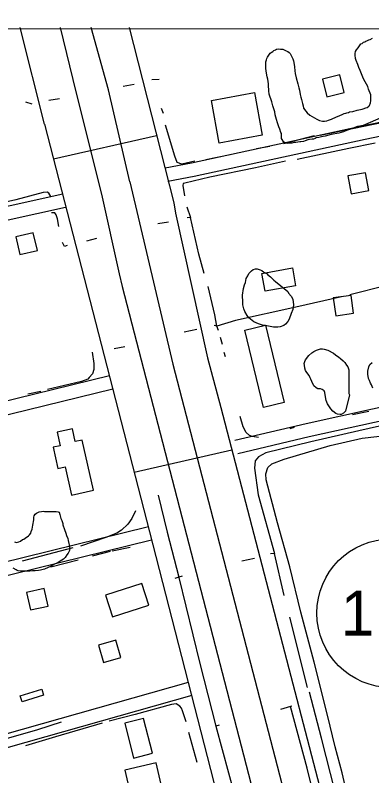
# Model space of a CAD drawing. Extents: x 3297753 to 3335611, y 652252 to 677623.
# Drawn here: x 3303757 to 3304548, y 674159 to 675847 of the extents above; entities that cross this region are included whole.
import ezdxf

# ---------------------------------------------------------------- set-up
doc = ezdxf.new("R2010")
doc.units = 0
for name, color, linetype in [('V-BLDG-OTLN', 7, 'Continuous'), ('V-DTCH-CNTR', 7, 'Continuous'), ('V-GRID-FRAM', 7, 'Continuous'), ('V-ROAD-CNTR', 7, 'Continuous'), ('V-ROAD-IDEN', 7, 'Continuous'), ('V-SITE-VEGE', 7, 'Continuous'), ('V-TOPO-SHOR', 7, 'Continuous')]:
    doc.layers.add(name, color=color, linetype=linetype)

msp = doc.modelspace()

# ---------------------------------------------------------------- linework, layer by layer
at = {"layer": 'V-BLDG-OTLN'}
for points in [[(3304448.3, 675666.1), (3304487.1, 675675.7), (3304477.5, 675714.5), (3304438.7, 675704.9)], [(3304287.5, 675675.3), (3304304.7, 675580.7), (3304209.3, 675563.3), (3304192.1, 675658)], [(3304534.4, 675497.5), (3304495.1, 675490.2), (3304502.4, 675450.9), (3304541.7, 675458.2)], [(3303767, 675315.9), (3303805.9, 675325.1), (3303796.6, 675364.1), (3303757.7, 675354.8)], [(3304379.1, 675246.7), (3304311.4, 675234.4), (3304304.3, 675273.7), (3304372, 675286)], [(3304462.7, 675219.7), (3304468.1, 675180.1), (3304507.8, 675185.5), (3304502.3, 675225.2)], [(3304307.6, 674976.1), (3304266.2, 675147.8), (3304312.4, 675158.9), (3304353.8, 674987.3)], [(3303930.2, 674792.8), (3303905.1, 674904.1), (3303890, 674900.7), (3303883.6, 674929.2), (3303849.5, 674921.5), (3303856.3, 674891.6), (3303840.6, 674888), (3303851.2, 674840.9), (3303867.6, 674844.6), (3303881.7, 674781.9)], [(3303820.5, 674574.7), (3303781.5, 674565.9), (3303790.4, 674526.9), (3303829.4, 674535.7)], [(3304037.9, 674585.7), (3303957, 674559.7), (3303972.3, 674511.8), (3304053.3, 674537.8)], [(3303952.9, 674410.3), (3303991.2, 674421.6), (3303979.9, 674460), (3303941.6, 674448.7)], [(3303819.7, 674337.8), (3303771.9, 674323.2), (3303767.8, 674336.6), (3303815.6, 674351.2)], [(3304061, 674208.8), (3304041.5, 674286.2), (3303999.8, 674275.7), (3304019.2, 674198.3)], [(3304087.4, 674110.8), (3304069.4, 674187.6), (3303999.7, 674171.3), (3304017.6, 674094.5)]]:
    msp.add_lwpolyline(points, close=True, dxfattribs=at)
at = {"layer": 'V-DTCH-CNTR'}
msp.add_lwpolyline([(3304563.6, 673850.9), (3304544.1, 673933.5), (3304517.4, 674019.1), (3304501.1, 674085.5), (3304482.7, 674165.2), (3304466.7, 674222.8), (3304449.5, 674293.3), (3304420, 674411.1), (3304390.5, 674521.8), (3304366.3, 674622.7), (3304338.5, 674720.1), (3304314, 674815.5), (3304313, 674829.1), (3304317, 674842.9), (3304325.9, 674851.3), (3304353.4, 674861.8), (3304455.8, 674891.9), (3304526.6, 674908.6), (3304585.3, 674914.6)], dxfattribs=at)
at = {"layer": 'V-GRID-FRAM'}
msp.add_lwpolyline([(3301859.6, 675814.9), (3333399.1, 675847), (3333425.5, 657662.7), (3301870.2, 657630.6), (3301859.6, 675814.9)], dxfattribs=at)
at = {"layer": 'V-ROAD-CNTR'}
for points in [[(3303821.3, 675605.4), (3303767.9, 675819.8)], [(3303856, 675819.9), (3303891, 675676.9), (3303948.2, 675450)], [(3304010.7, 675477.2), (3303963.9, 675681.3), (3303925, 675819.9)], [(3304009.8, 675820), (3304108.4, 675430.4)], [(3304089.7, 675508.3), (3304148.2, 675519), (3304527.1, 675601.4), (3304971.6, 675693.4), (3305454.6, 675794.1), (3305573.8, 675819.4)], [(3304095.1, 675478.8), (3304154.1, 675489.5), (3304533.3, 675572.1), (3304977.7, 675664.1), (3305460.7, 675764.7), (3305706.2, 675816.9)], [(3303821.3, 675605.4), (3304055, 674700.5), (3304303.9, 673729.3), (3304378.9, 673425.1)], [(3303841.2, 675528.3), (3304070.5, 675580.3)], [(3304244, 674903.5), (3304402.3, 674940.9), (3304844.1, 675038.3), (3305362.9, 675156.1), (3305778.6, 675248.1), (3306368, 675380.8), (3306791.3, 675474.1), (3306957.4, 675510.8), (3306994.4, 675513.7)], [(3304010.7, 675477.2), (3304106.3, 675072.8)], [(3303862, 675449.8), (3302685.8, 675189.6)], [(3303948.2, 675450), (3303987.5, 675272.7), (3303994.3, 675245)], [(3303868.5, 675420.5), (3302823, 675189.2)], [(3304108.4, 675430.4), (3304112.3, 675407.4), (3304183.2, 675086.4), (3304212.9, 674976)], [(3303994.3, 675245), (3304427.9, 673571.6)], [(3304250.9, 674874.3), (3304409, 674911.7), (3304850.7, 675009), (3305220.4, 675093)], [(3304106.3, 675072.8), (3304480.7, 673631.5)], [(3303965.9, 675046.3), (3303633.6, 674964.9)], [(3303973, 675017.2), (3303293.6, 674850.6)], [(3304212.9, 674976), (3304560.4, 673644.5)], [(3304020.9, 674832.5), (3304237.3, 674882.4)], [(3303010.3, 674455.3), (3304052.2, 674712)], [(3301875.7, 674135.6), (3301923.9, 674149.7), (3302004.8, 674177.6), (3302130.2, 674202.7), (3302342, 674257.5), (3302824.3, 674378.5), (3304059.4, 674682.9)], [(3304140.4, 674365.9), (3302754.4, 673973.9)], [(3304148.5, 674337), (3302762.8, 673945.1)]]:
    msp.add_lwpolyline(points, dxfattribs=at)
at = {"layer": 'V-ROAD-IDEN'}
msp.add_circle((3304591.1, 674519.8), 165, dxfattribs=at)
at = {"layer": 'V-SITE-VEGE'}
for p, q in [((3304526.8, 675784.3), (3304529.6, 675787.1)), ((3304529.6, 675787.1), (3304532.9, 675788.1)), ((3304532.9, 675788.1), (3304535.2, 675789.7)), ((3304535.2, 675789.7), (3304538.5, 675790.8)), ((3304538.5, 675790.8), (3304541.3, 675792.4)), ((3304541.3, 675792.4), (3304544.7, 675793.4)), ((3304544.7, 675793.4), (3304549.7, 675796.1)), ((3304330.7, 675768.4), (3304334, 675770)), ((3304334, 675770), (3304336.3, 675771.6)), ((3304336.3, 675771.6), (3304341.8, 675772.1)), ((3304341.8, 675772.1), (3304345.7, 675772)), ((3304345.7, 675772), (3304350.7, 675771.3)), ((3304350.7, 675771.3), (3304353.4, 675770.2)), ((3304353.4, 675770.2), (3304358.4, 675767.9)), ((3304512, 675766.8), (3304514.3, 675770.1)), ((3304514.3, 675770.1), (3304517.7, 675774.5)), ((3304517.7, 675774.5), (3304524, 675783.3)), ((3304524, 675783.3), (3304526.8, 675784.3)), ((3304314.8, 675750.9), (3304316.5, 675753.6)), ((3304316.5, 675753.6), (3304318.2, 675755.8)), ((3304318.2, 675755.8), (3304322.2, 675762.4)), ((3304322.2, 675762.4), (3304324.5, 675764.6)), ((3304324.5, 675764.6), (3304328.4, 675766.7)), ((3304328.4, 675766.7), (3304330.7, 675768.4)), ((3304358.4, 675767.9), (3304361.7, 675766.2)), ((3304361.7, 675766.2), (3304364.4, 675763.9)), ((3304364.4, 675763.9), (3304367.2, 675762.2)), ((3304367.2, 675762.2), (3304368.2, 675759.4)), ((3304368.2, 675759.4), (3304370.9, 675754.9)), ((3304370.9, 675754.9), (3304373.1, 675750.4)), ((3304511.3, 675758), (3304511.4, 675761.9)), ((3304511.8, 675751.3), (3304511.3, 675758)), ((3304511.4, 675761.9), (3304512, 675766.8)), ((3304312.8, 675733.2), (3304313, 675743.7)), ((3304313, 675743.7), (3304314.2, 675748.1)), ((3304314.2, 675748.1), (3304314.8, 675750.9)), ((3304373.1, 675750.4), (3304374.6, 675745.4)), ((3304374.6, 675745.4), (3304375.6, 675737.6)), ((3304375.6, 675737.6), (3304376.6, 675732.1)), ((3304513.3, 675746.3), (3304511.8, 675751.3)), ((3304517.1, 675737.9), (3304513.3, 675746.3)), ((3304519.2, 675731.2), (3304517.1, 675737.9)), ((3304312.8, 675728.7), (3304312.8, 675733.2)), ((3304313.8, 675723.2), (3304312.8, 675728.7)), ((3304314.3, 675718.7), (3304313.8, 675723.2)), ((3304376.6, 675732.1), (3304377, 675723.7)), ((3304377, 675723.7), (3304378, 675717.6)), ((3304522.4, 675724.5), (3304519.2, 675731.2)), ((3304525.6, 675717.2), (3304522.4, 675724.5)), ((3304315.8, 675710.4), (3304314.3, 675718.7)), ((3304317.4, 675705.4), (3304315.8, 675710.4)), ((3304318.8, 675694.8), (3304317.4, 675705.4)), ((3304378, 675717.6), (3304380.1, 675708.1)), ((3304380.1, 675708.1), (3304383.7, 675694.8)), ((3304529.8, 675705.5), (3304525.6, 675717.2)), ((3304533.6, 675698.8), (3304529.8, 675705.5)), ((3304318.7, 675687.6), (3304318.8, 675694.8)), ((3304319.7, 675683.7), (3304318.7, 675687.6)), ((3304383.7, 675694.8), (3304385.8, 675685.8)), ((3304385.8, 675685.8), (3304387.4, 675680.3)), ((3304539, 675688.7), (3304533.6, 675698.8)), ((3304541.1, 675682.6), (3304539, 675688.7)), ((3304319.7, 675679.2), (3304319.7, 675683.7)), ((3304320.6, 675672), (3304319.7, 675679.2)), ((3304326.4, 675654.7), (3304320.6, 675672)), ((3304387.4, 675680.3), (3304389.4, 675670.8)), ((3304389.4, 675670.8), (3304390.4, 675665.2)), ((3304545.8, 675670.3), (3304541.1, 675682.6)), ((3304546.3, 675663.6), (3304545.8, 675670.3)), ((3304328.5, 675645.8), (3304326.4, 675654.7)), ((3304390.4, 675665.2), (3304392, 675659.7)), ((3304392, 675659.7), (3304394.1, 675651.3)), ((3304394.1, 675651.3), (3304395.6, 675645.7)), ((3304543.2, 675646.5), (3304545.5, 675652.5)), ((3304545.5, 675652.5), (3304546.2, 675657)), ((3304546.2, 675657), (3304546.3, 675663.6)), ((3304332.7, 675632.4), (3304328.5, 675645.8)), ((3304395.6, 675645.7), (3304396.7, 675640.7)), ((3304396.7, 675640.7), (3304401.5, 675634)), ((3304505.8, 675633.3), (3304515.8, 675636.4)), ((3304515.8, 675636.4), (3304526.4, 675638.4)), ((3304526.4, 675638.4), (3304529.2, 675639.5)), ((3304529.2, 675639.5), (3304534.8, 675641.1)), ((3304534.8, 675641.1), (3304537.6, 675642.1)), ((3304537.6, 675642.1), (3304541.5, 675644.8)), ((3304541.5, 675644.8), (3304543.2, 675646.5)), ((3304333.7, 675625.7), (3304332.7, 675632.4)), ((3304336.3, 675615.2), (3304333.7, 675625.7)), ((3304401.5, 675634), (3304404.8, 675630.6)), ((3304404.8, 675630.6), (3304410.8, 675624.9)), ((3304410.8, 675624.9), (3304426.2, 675616.3)), ((3304458.4, 675616.3), (3304469.5, 675621.7)), ((3304469.5, 675621.7), (3304475.7, 675623.8)), ((3304475.7, 675623.8), (3304483.5, 675627.5)), ((3304483.5, 675627.5), (3304486.9, 675628.6)), ((3304486.9, 675628.6), (3304490.8, 675629.6)), ((3304490.8, 675629.6), (3304493, 675630.7)), ((3304493, 675630.7), (3304496.3, 675631.2)), ((3304496.3, 675631.2), (3304498.6, 675632.3)), ((3304498.6, 675632.3), (3304505.8, 675633.3)), ((3304571.6, 675620.4), (3304528.6, 675602.3)), ((3304338.9, 675608.5), (3304336.3, 675615.2)), ((3304342.1, 675599.5), (3304338.9, 675608.5)), ((3304426.2, 675616.3), (3304431.7, 675613.5)), ((3304431.7, 675613.5), (3304438.9, 675611.7)), ((3304438.9, 675611.7), (3304443.3, 675611.6)), ((3304443.3, 675611.6), (3304448.3, 675612.6)), ((3304448.3, 675612.6), (3304452.2, 675614.2)), ((3304452.2, 675614.2), (3304458.4, 675616.3)), ((3304521.9, 675600.8), (3304516.3, 675599.8)), ((3304528.6, 675602.3), (3304521.9, 675600.8)), ((3304344.2, 675593.9), (3304342.1, 675599.5)), ((3304346.3, 675586.7), (3304344.2, 675593.9)), ((3304347.4, 675584.5), (3304346.3, 675586.7)), ((3304347.8, 675577.2), (3304347.4, 675584.5)), ((3304475, 675585.5), (3304457.8, 675582.5)), ((3304485.6, 675588.1), (3304475, 675585.5)), ((3304491.7, 675590.8), (3304485.6, 675588.1)), ((3304506.8, 675596.6), (3304491.7, 675590.8)), ((3304516.3, 675599.8), (3304506.8, 675596.6)), ((3304347.8, 675573.4), (3304347.8, 675577.2)), ((3304352.6, 675564.9), (3304347.8, 675573.4)), ((3304396.5, 675566.9), (3304390.9, 675565.9)), ((3304400.4, 675568.5), (3304396.5, 675566.9)), ((3304406.5, 675570.1), (3304400.4, 675568.5)), ((3304409.9, 675571.1), (3304406.5, 675570.1)), ((3304415.4, 675571.6), (3304409.9, 675571.1)), ((3304418.7, 675572.1), (3304415.4, 675571.6)), ((3304422.7, 675573.7), (3304418.7, 675572.1)), ((3304424.9, 675574.8), (3304422.7, 675573.7)), ((3304430.5, 675575.8), (3304424.9, 675574.8)), ((3304436.6, 675577.3), (3304430.5, 675575.8)), ((3304444.4, 675578.9), (3304436.6, 675577.3)), ((3304457.8, 675582.5), (3304444.4, 675578.9)), ((3304356.4, 675562.7), (3304352.6, 675564.9)), ((3304362, 675562.6), (3304356.4, 675562.7)), ((3304366.4, 675563), (3304362, 675562.6)), ((3304370.3, 675563), (3304366.4, 675563)), ((3304375.3, 675564.5), (3304370.3, 675563)), ((3304379.8, 675564.5), (3304375.3, 675564.5)), ((3304388.7, 675566), (3304379.8, 675564.5)), ((3304390.9, 675565.9), (3304388.7, 675566))]:
    msp.add_line(p, q, dxfattribs=at)
for points in [[(3304361.5, 675233.6), (3304363.4, 675229.9), (3304368.9, 675223.4), (3304372.6, 675217.1), (3304374.2, 675204.2), (3304372.6, 675194.2), (3304369.3, 675184.7), (3304364.4, 675172.7), (3304362, 675167.4), (3304356.7, 675161.1), (3304352.5, 675158.3), (3304344.9, 675155.6), (3304339.3, 675154.9), (3304329.8, 675154.9), (3304311.5, 675158), (3304305.3, 675159.4), (3304296.7, 675162), (3304286.5, 675166.2), (3304275.2, 675175.2), (3304271.5, 675180.3), (3304266.4, 675189.2), (3304264.1, 675195), (3304262, 675204), (3304261.6, 675210.3), (3304260.9, 675225.6), (3304263.5, 675240.4), (3304265.6, 675248.5), (3304267.5, 675254), (3304268.4, 675258.4), (3304269.6, 675262.6), (3304272.9, 675268.9), (3304275.4, 675273.5), (3304281, 675279.7), (3304285, 675282.3), (3304289.8, 675283.9), (3304293.8, 675283.9), (3304300, 675282.2), (3304303.7, 675280.4), (3304308.8, 675276.9), (3304311.6, 675275.2), (3304315.5, 675272.7), (3304317.6, 675270.8), (3304323.6, 675266.2), (3304327.5, 675261.8), (3304330.5, 675259), (3304334.5, 675256)], [(3304489.7, 674968), (3304485.5, 674963.6), (3304480.1, 674960.8), (3304477.6, 674960.6), (3304472.3, 674961.3), (3304468.3, 674963.1), (3304461.9, 674968), (3304457.2, 674973.4), (3304449.8, 674984.3), (3304446.9, 674992.2), (3304445.3, 675000), (3304443.9, 675009.6), (3304442.3, 675013.5), (3304437.6, 675016.3), (3304434.2, 675017.5), (3304428.2, 675017.9), (3304424.7, 675020), (3304419.8, 675024.7), (3304414.8, 675033.7), (3304412.9, 675039.1), (3304411.5, 675042.3), (3304409, 675047), (3304403.7, 675053.9), (3304401.2, 675058.8), (3304399.8, 675063.7), (3304398.6, 675070.2), (3304398.2, 675074.1), (3304399.6, 675078.7), (3304401.2, 675082), (3304408.7, 675091.9), (3304414.7, 675097.5), (3304419.3, 675100.7), (3304425.6, 675103.7), (3304429.5, 675105.3), (3304434.6, 675106.2), (3304438.4, 675106.2), (3304442.3, 675105.7), (3304450.2, 675103.6), (3304462.9, 675096.6), (3304467.8, 675093.4), (3304474.9, 675088), (3304478.6, 675084.8), (3304484.9, 675079.9), (3304488.3, 675075.9), (3304492.3, 675070.4), (3304494.6, 675066.7), (3304496.9, 675060.2), (3304497.5, 675054.6), (3304497.4, 675007.1), (3304498.6, 675004.1)]]:
    msp.add_lwpolyline(points, close=True, dxfattribs=at)
for points in [[(3304550.7, 675019), (3304547.3, 675026.9), (3304545.2, 675030.4), (3304542.9, 675036.4), (3304541.1, 675040.6), (3304539.2, 675050.5), (3304539.5, 675057.3), (3304541.4, 675066.8), (3304543.7, 675071.6), (3304548.8, 675076)], [(3303791, 674697.5), (3303792.1, 674701.4), (3303794, 674706.6), (3303796, 674715.4), (3303797.9, 674726.7), (3303797.9, 674733), (3303798.5, 674735.7), (3303800.7, 674739.6), (3303803.5, 674742), (3303807.9, 674743.9), (3303809.8, 674745), (3303815, 674745.3), (3303818.6, 674746.1), (3303821.9, 674745.8), (3303845.5, 674745.8), (3303847.7, 674745.2), (3303851.6, 674744.9), (3303854, 674743.8), (3303855.7, 674739.1), (3303856.2, 674735.8), (3303858.1, 674730.1), (3303860.3, 674725.4), (3303862.2, 674718.8), (3303862.5, 674715.8), (3303866, 674705.3), (3303869.3, 674697.3), (3303870.6, 674692.4), (3303873.4, 674685.2), (3303873.9, 674681.4), (3303875.5, 674674.5), (3303876.4, 674671.8), (3303878, 674663.5), (3303877.4, 674658.6), (3303873.8, 674652.8), (3303870.8, 674649.2), (3303867.2, 674643.5), (3303863.4, 674639.6), (3303856.5, 674635), (3303852.1, 674632.3), (3303842.4, 674627.6), (3303836.1, 674624.3), (3303821.8, 674617.8), (3303812.7, 674615.6), (3303808.1, 674614.8), (3303800.9, 674614), (3303794.9, 674613.7), (3303788.8, 674613.2), (3303772.3, 674612.7), (3303769.3, 674613), (3303763, 674614.1), (3303761.1, 674614.9), (3303758.9, 674616), (3303752.3, 674619.6)], [(3303755.2, 674677.9), (3303759.3, 674676.7), (3303764.8, 674677.8), (3303768.4, 674679.7), (3303773.1, 674683), (3303775.8, 674684.4), (3303778.9, 674686.3), (3303786.3, 674691.5), (3303788.2, 674693.7), (3303791, 674697.5)]]:
    msp.add_lwpolyline(points, dxfattribs=at)
at = {"layer": 'V-TOPO-SHOR'}
for p, q in [((3304076.3, 675704.3), (3304059.6, 675703.5)), ((3304020.7, 675693), (3303996, 675688.7)), ((3303793.9, 675649.5), (3303779.8, 675654)), ((3303854.8, 675661.7), (3303831, 675657.4)), ((3304085.8, 675628.5), (3304081.4, 675640)), ((3304420.1, 675579.3), (3304352, 675561.6)), ((3304322, 675555.5), (3304292, 675550.3)), ((3304233.7, 675537.2), (3304179.9, 675525.9)), ((3304096.8, 675387.9), (3304072.9, 675383.6)), ((3303936.9, 675351.1), (3303914.8, 675345.8)), ((3304160, 675149.4), (3304131.6, 675143.2)), ((3304216.6, 675116.4), (3304212.2, 675131.5)), ((3303999.7, 675111), (3303975.9, 675106.7)), ((3304223.6, 675088.9), (3304220.1, 675098.7)), ((3303813.4, 675011.9), (3303784.3, 675005.8)), ((3304541.7, 674967.6), (3304505.6, 674959.7)), ((3304375.8, 674931.9), (3304366.1, 674929.2)), ((3303884.8, 674665.1), (3303771.8, 674635.4)), ((3303967.7, 674656.9), (3303927.1, 674646.4)), ((3304011.8, 674665.6), (3303972.1, 674657.8)), ((3304287.8, 674641.1), (3304259.5, 674635)), ((3304353.7, 674558.9), (3304331.9, 674652.5)), ((3303896.2, 674637.7), (3303835.3, 674622)), ((3304405.2, 674355), (3304365.9, 674511.2)), ((3304209, 674271.3), (3304202.1, 674269.1)), ((3304160.4, 674188.1), (3304142.1, 674255.2))]:
    msp.add_line(p, q, dxfattribs=at)
for points in [[(3304630.8, 675619.9), (3304551.7, 675604.7), (3304433.8, 675580.1)], [(3304155.2, 675523.3), (3304126.8, 675516.6), (3304116.2, 675520.2), (3304110.9, 675534.4), (3304090.1, 675602.9)], [(3304555.7, 675562.8), (3304496.8, 675551), (3304382.7, 675527.1)], [(3304356.3, 675522.8), (3304290.1, 675508.3), (3304188.5, 675487.3), (3304132.8, 675474.2), (3304129.3, 675473.4), (3304128.4, 675469), (3304132.4, 675446.3)], [(3303835.7, 675444.8), (3303831.2, 675452.4), (3303827.7, 675454.2), (3303818.8, 675453.3), (3303757.8, 675437.6), (3303678.2, 675419.2), (3303630.1, 675409.2)], [(3304137.7, 675421.5), (3304145.9, 675398.3), (3304138.5, 675397.6)], [(3303853.2, 675377.8), (3303850.5, 675394.9), (3303847.8, 675403.8), (3303844.3, 675408.2), (3303837.4, 675408.7)], [(3304176.3, 675273.4), (3304164.2, 675317), (3304145.9, 675398.3)], [(3303871.6, 675336.2), (3303866.2, 675333.9), (3303861.9, 675342.5)], [(3304892.5, 675317.7), (3304758.2, 675286.2), (3304581.5, 675247), (3304499.6, 675226.4)], [(3304204.4, 675157), (3304200, 675181.8), (3304185, 675245)], [(3304481, 675222.1), (3304379.2, 675198.9), (3304245.7, 675169.3), (3304204.4, 675157)], [(3304207.8, 675147.5), (3304204.4, 675157), (3304198.1, 675158.1)], [(3303927.4, 675098.9), (3303930.9, 675073.9), (3303930.9, 675060.6), (3303928.2, 675050.9), (3303921.1, 675043), (3303917.5, 675039.5), (3303903.4, 675034.2), (3303828.4, 675016.2)], [(3305190.3, 675078.7), (3305117.2, 675062.7), (3304995.3, 675034.8), (3304898.1, 675012.1), (3304796.5, 674986.8), (3304691.3, 674965), (3304610.9, 674944.9), (3304519, 674924.8), (3304413, 674900.4), (3304313.1, 674875.9), (3304296.3, 674867.1), (3304289.2, 674858.3), (3304287.4, 674841.6), (3304296.1, 674782.4), (3304331.9, 674652.5), (3304323.1, 674651.5)], [(3304296.4, 674910), (3304282.3, 674912.2), (3304277, 674914), (3304269.1, 674921.1), (3304262.9, 674933.5), (3304256, 674956)], [(3304073.9, 674781.8), (3304094, 674699.6), (3304119.8, 674599.4)], [(3304023.5, 674746.7), (3304015.7, 674729.9), (3304006.8, 674717.6), (3303992.6, 674704.4), (3303982, 674697.3), (3303958.1, 674687.7), (3303901.5, 674668.6)], [(3304127.1, 674601.8), (3304119.8, 674599.4), (3304111.2, 674596.6)], [(3304119.8, 674599.4), (3304120, 674598.7), (3304166.3, 674407.9), (3304202.1, 674269.1), (3304244.1, 674113.6), (3304288.5, 673934.6)], [(3304571.4, 673718.4), (3304557.4, 673771.4), (3304537.3, 673848.3), (3304510.2, 673955.2), (3304466.5, 674123.1), (3304436.8, 674242.4), (3304409.5, 674344.4)], [(3304136, 674279), (3304128, 674302.9), (3304125.4, 674309.1), (3304121.9, 674313.5), (3304114, 674318.8), (3304103.4, 674317.1), (3304022.9, 674295.2), (3303965.4, 674280.1)], [(3304370.7, 674313.6), (3304368, 674312.8), (3304345.1, 674305.8)], [(3304430.9, 674070.9), (3304404.7, 674176), (3304368, 674312.8)], [(3303858.3, 674277.7), (3303806, 674261), (3303699.7, 674230.3), (3303633.2, 674211)], [(3303949.5, 674275.7), (3303846.2, 674245.4), (3303779.4, 674225.7)]]:
    msp.add_lwpolyline(points, dxfattribs=at)

# ---------------------------------------------------------------- texts
at = {"layer": 'V-ROAD-IDEN'}
msp.add_text(' 1 ', height=100, rotation=359.9007, dxfattribs=at).set_placement((3304442.2, 674470.1))

doc.saveas('drawing.dxf')
